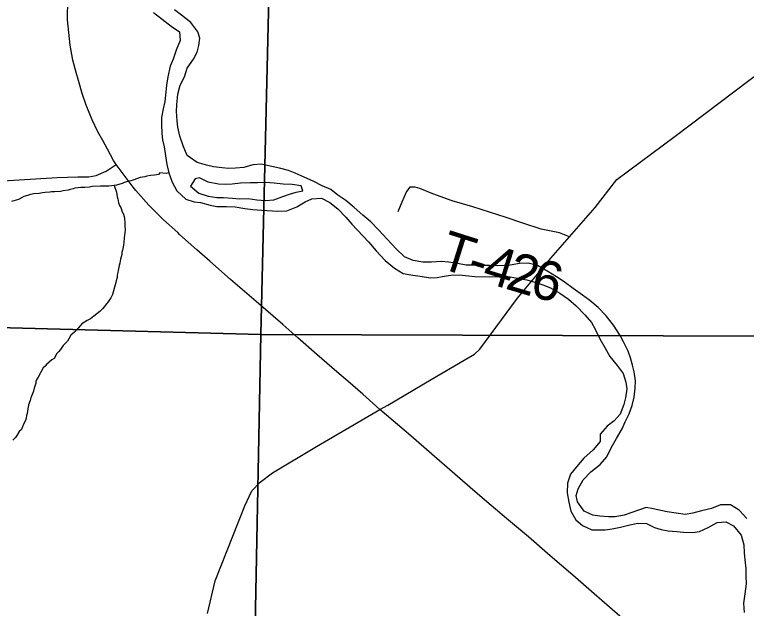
# Model space of a CAD drawing. Extents: x 0 to 34, y -2.3 to 22.
# Drawn here: x 5.006 to 6.069, y 17.952 to 18.814 of the extents above; entities that cross this region are included whole.
import ezdxf

# ---------------------------------------------------------------- set-up
doc = ezdxf.new("R2010")
doc.units = 0
for name, color, linetype in [('GM_X_County_Road', 7, 'Continuous'), ('GM_X_Major_River', 7, 'Continuous'), ('GM_X_Minor_River', 7, 'Continuous'), ('GM_X_Section', 7, 'Continuous'), ('GM_X_Township_Road', 7, 'Continuous'), ('GM_X_Township_Road_Text', 7, 'Continuous'), ('GM_X_US_Route', 7, 'Continuous')]:
    doc.layers.add(name, color=color, linetype=linetype)

msp = doc.modelspace()

# ---------------------------------------------------------------- linework, layer by layer
at = {"layer": 'GM_X_County_Road'}
for p, q in [((5.9656, 18.6376), (6.1106, 18.7475)), ((5.8806, 18.5744), (5.9656, 18.6376)), ((5.8491, 18.534), (5.8806, 18.5744)), ((5.812, 18.4912), (5.8491, 18.534)), ((5.7848, 18.4604), (5.812, 18.4912)), ((5.7365, 18.4021), (5.7848, 18.4604)), ((5.6899, 18.3394), (5.7365, 18.4021)), ((5.6819, 18.3282), (5.6899, 18.3394)), ((5.6741, 18.3209), (5.6819, 18.3282)), ((5.659, 18.3122), (5.6741, 18.3209)), ((5.6112, 18.2843), (5.659, 18.3122)), ((5.5479, 18.2468), (5.6112, 18.2843)), ((5.4446, 18.1868), (5.5363, 18.2406)), ((5.5363, 18.2406), (5.5479, 18.2468)), ((5.3805, 18.1488), (5.4446, 18.1868)), ((5.3628, 18.1351), (5.3805, 18.1488)), ((5.3507, 18.1225), (5.3628, 18.1351)), ((5.3403, 18.1007), (5.3507, 18.1225)), ((5.2972, 17.992), (5.3403, 18.1007)), ((5.286, 17.9445), (5.2972, 17.992))]:
    msp.add_line(p, q, dxfattribs=at)
at = {"layer": 'GM_X_Major_River'}
for p, q in [((5.2075, 18.8173), (5.2201, 18.8074)), ((5.2484, 18.813), (5.2384, 18.8209)), ((5.2201, 18.8074), (5.2335, 18.7971)), ((5.2618, 18.8028), (5.2484, 18.813)), ((5.272, 18.7891), (5.2618, 18.8028)), ((5.2335, 18.7971), (5.2454, 18.7888)), ((5.2454, 18.7888), (5.2462, 18.7762)), ((5.2748, 18.7796), (5.272, 18.7891)), ((5.2462, 18.7762), (5.2408, 18.7623)), ((5.2737, 18.7693), (5.2748, 18.7796)), ((5.2408, 18.7623), (5.2362, 18.7495)), ((5.2711, 18.7595), (5.2737, 18.7693)), ((5.2659, 18.7494), (5.2711, 18.7595)), ((5.2321, 18.739), (5.2287, 18.7239)), ((5.2362, 18.7495), (5.2321, 18.739)), ((5.2564, 18.7364), (5.2659, 18.7494)), ((5.2526, 18.7235), (5.2564, 18.7364)), ((5.2287, 18.7239), (5.2264, 18.7118)), ((5.2465, 18.7116), (5.2526, 18.7235)), ((5.2264, 18.7118), (5.2257, 18.7019)), ((5.2431, 18.6987), (5.2465, 18.7116)), ((5.2257, 18.7019), (5.2242, 18.6879)), ((5.2415, 18.6832), (5.2431, 18.6987)), ((5.2242, 18.6879), (5.2216, 18.6773)), ((5.2216, 18.6773), (5.2193, 18.6644)), ((5.2412, 18.6733), (5.2415, 18.6832)), ((5.242, 18.66), (5.2412, 18.6733)), ((5.2193, 18.6644), (5.2194, 18.6546)), ((5.2194, 18.6546), (5.2198, 18.6416)), ((5.2428, 18.6504), (5.242, 18.66)), ((5.2459, 18.6374), (5.2428, 18.6504)), ((5.2198, 18.6416), (5.2206, 18.6321)), ((5.2508, 18.6236), (5.2459, 18.6374)), ((5.2206, 18.6321), (5.223, 18.6221)), ((5.223, 18.6221), (5.2253, 18.6088)), ((5.2564, 18.6097), (5.2508, 18.6236)), ((5.2253, 18.6088), (5.2272, 18.5962)), ((5.2713, 18.5994), (5.2564, 18.6097)), ((5.2272, 18.5962), (5.2299, 18.5843)), ((5.2845, 18.5952), (5.2713, 18.5994)), ((5.2947, 18.593), (5.2845, 18.5952)), ((5.3072, 18.5915), (5.2947, 18.593)), ((5.3167, 18.5905), (5.3072, 18.5915)), ((5.327, 18.5909), (5.3167, 18.5905)), ((5.3391, 18.5921), (5.327, 18.5909)), ((5.3522, 18.5959), (5.3391, 18.5921)), ((5.364, 18.5967), (5.3522, 18.5959)), ((5.3772, 18.594), (5.364, 18.5967)), ((5.3908, 18.5913), (5.3772, 18.594)), ((5.4036, 18.5876), (5.3908, 18.5913)), ((5.2299, 18.5843), (5.2348, 18.5708)), ((5.4134, 18.5838), (5.4036, 18.5876)), ((5.4265, 18.5781), (5.4134, 18.5838)), ((5.2348, 18.5708), (5.2416, 18.5581)), ((5.268, 18.5756), (5.2616, 18.5651)), ((5.2745, 18.5769), (5.268, 18.5756)), ((5.2872, 18.5708), (5.2745, 18.5769)), ((5.3019, 18.5677), (5.2872, 18.5708)), ((5.3339, 18.5691), (5.3217, 18.5679)), ((5.348, 18.5698), (5.3339, 18.5691)), ((5.3586, 18.5699), (5.348, 18.5698)), ((5.3704, 18.5703), (5.3586, 18.5699)), ((5.3829, 18.5695), (5.3704, 18.5703)), ((5.3962, 18.5676), (5.3829, 18.5695)), ((5.4404, 18.5716), (5.4265, 18.5781)), ((5.4527, 18.5652), (5.4404, 18.5716)), ((5.2616, 18.5651), (5.2734, 18.5549)), ((5.3122, 18.5674), (5.3019, 18.5677)), ((5.3217, 18.5679), (5.3122, 18.5674)), ((5.4091, 18.5672), (5.3962, 18.5676)), ((5.422, 18.5653), (5.4091, 18.5672)), ((5.4149, 18.5564), (5.4244, 18.5584)), ((5.4244, 18.5584), (5.422, 18.5653)), ((5.4655, 18.5599), (5.4527, 18.5652)), ((5.4755, 18.552), (5.4655, 18.5599)), ((5.2416, 18.5581), (5.2546, 18.5463)), ((5.2734, 18.5549), (5.287, 18.5503)), ((5.287, 18.5503), (5.2995, 18.5484)), ((5.2995, 18.5484), (5.3094, 18.5485)), ((5.3094, 18.5485), (5.3226, 18.5473)), ((5.3826, 18.5452), (5.3957, 18.5498)), ((5.3957, 18.5498), (5.4053, 18.5533)), ((5.4053, 18.5533), (5.4149, 18.5564)), ((5.4871, 18.544), (5.4755, 18.552)), ((5.2546, 18.5463), (5.2666, 18.5421)), ((5.2666, 18.5421), (5.2761, 18.5411)), ((5.2761, 18.5411), (5.29, 18.5373)), ((5.29, 18.5373), (5.2999, 18.5355)), ((5.3226, 18.5473), (5.3321, 18.5467)), ((5.3321, 18.5467), (5.345, 18.5471)), ((5.345, 18.5471), (5.3579, 18.5452)), ((5.3579, 18.5452), (5.3704, 18.544)), ((5.3704, 18.544), (5.3826, 18.5452)), ((5.4161, 18.5347), (5.4281, 18.542)), ((5.4281, 18.542), (5.4377, 18.5466)), ((5.4377, 18.5466), (5.4518, 18.5473)), ((5.4518, 18.5473), (5.4638, 18.5413)), ((5.4638, 18.5413), (5.4753, 18.5318)), ((5.4993, 18.5342), (5.4871, 18.544)), ((5.2999, 18.5355), (5.3135, 18.5354)), ((5.3135, 18.5354), (5.3264, 18.5347)), ((5.3264, 18.5347), (5.3404, 18.5324)), ((5.3404, 18.5324), (5.3522, 18.5309)), ((5.3522, 18.5309), (5.3647, 18.5301)), ((5.3647, 18.5301), (5.3882, 18.5287)), ((5.3882, 18.5287), (5.4015, 18.5291)), ((5.4015, 18.5291), (5.4161, 18.5347)), ((5.4753, 18.5318), (5.4871, 18.5197)), ((5.5119, 18.5228), (5.4993, 18.5342)), ((5.4871, 18.5197), (5.4959, 18.5096)), ((5.5234, 18.5133), (5.5119, 18.5228)), ((5.4959, 18.5096), (5.5199, 18.4841)), ((5.5345, 18.5016), (5.5234, 18.5133)), ((5.5595, 18.4742), (5.5345, 18.5016)), ((5.5199, 18.4841), (5.5309, 18.4709)), ((5.5721, 18.4621), (5.5595, 18.4742)), ((5.5309, 18.4709), (5.5442, 18.4568)), ((5.5442, 18.4568), (5.5579, 18.4458)), ((5.5848, 18.4571), (5.5721, 18.4621)), ((5.5988, 18.4548), (5.5848, 18.4571)), ((5.6117, 18.4548), (5.5988, 18.4548)), ((5.6262, 18.4555), (5.6117, 18.4548)), ((5.6361, 18.4545), (5.6262, 18.4555)), ((5.6493, 18.4526), (5.6361, 18.4545)), ((5.6618, 18.4503), (5.6493, 18.4526)), ((5.7394, 18.4526), (5.7256, 18.4503)), ((5.7519, 18.453), (5.7394, 18.4526)), ((5.7655, 18.4499), (5.7519, 18.453)), ((5.5579, 18.4458), (5.5702, 18.4382)), ((5.6732, 18.45), (5.6618, 18.4503)), ((5.6827, 18.4497), (5.6732, 18.45)), ((5.6959, 18.4497), (5.6827, 18.4497)), ((5.7077, 18.4493), (5.6959, 18.4497)), ((5.7256, 18.4503), (5.7077, 18.4493)), ((5.7804, 18.4411), (5.7655, 18.4499)), ((5.5702, 18.4382), (5.5842, 18.4355)), ((5.5842, 18.4355), (5.5952, 18.4344)), ((5.5952, 18.4344), (5.6099, 18.4317)), ((5.6099, 18.4317), (5.6198, 18.4321)), ((5.6198, 18.4321), (5.6298, 18.4341)), ((5.6298, 18.4341), (5.6397, 18.4357)), ((5.6397, 18.4357), (5.6519, 18.4362)), ((5.6519, 18.4362), (5.6651, 18.4346)), ((5.6651, 18.4346), (5.6746, 18.434)), ((5.6746, 18.434), (5.6951, 18.4334)), ((5.6951, 18.4334), (5.705, 18.4338)), ((5.705, 18.4338), (5.716, 18.4339)), ((5.716, 18.4339), (5.7259, 18.4332)), ((5.7259, 18.4332), (5.7365, 18.4314)), ((5.7365, 18.4314), (5.7501, 18.4291)), ((5.7931, 18.4335), (5.7804, 18.4411)), ((5.8043, 18.426), (5.7931, 18.4335)), ((5.7501, 18.4291), (5.7614, 18.4257)), ((5.7614, 18.4257), (5.7734, 18.4216)), ((5.7734, 18.4216), (5.7843, 18.4174)), ((5.8173, 18.4165), (5.8043, 18.426)), ((5.7843, 18.4174), (5.7978, 18.4098)), ((5.7978, 18.4098), (5.8104, 18.4007)), ((5.8307, 18.4066), (5.8173, 18.4165)), ((5.8104, 18.4007), (5.8215, 18.3912)), ((5.8415, 18.399), (5.8307, 18.4066)), ((5.8538, 18.3888), (5.8415, 18.399)), ((5.8215, 18.3912), (5.8341, 18.3783)), ((5.8652, 18.3767), (5.8538, 18.3888)), ((5.8341, 18.3783), (5.844, 18.367)), ((5.844, 18.367), (5.8494, 18.3573)), ((5.8758, 18.363), (5.8652, 18.3767)), ((5.8494, 18.3573), (5.8562, 18.3431)), ((5.8856, 18.3483), (5.8758, 18.363)), ((5.8903, 18.3387), (5.8856, 18.3483)), ((5.8562, 18.3431), (5.8631, 18.3307)), ((5.8971, 18.3255), (5.8903, 18.3387)), ((5.8631, 18.3307), (5.8703, 18.3176)), ((5.9006, 18.3155), (5.8971, 18.3255)), ((5.8703, 18.3176), (5.8813, 18.3047)), ((5.9034, 18.3052), (5.9006, 18.3155)), ((5.8813, 18.3047), (5.8897, 18.293)), ((5.9057, 18.2952), (5.9034, 18.3052)), ((5.8897, 18.293), (5.8939, 18.2804)), ((5.908, 18.2822), (5.9057, 18.2952)), ((5.9073, 18.2716), (5.908, 18.2822)), ((5.8939, 18.2804), (5.8951, 18.2708)), ((5.9058, 18.2587), (5.9073, 18.2716)), ((5.8951, 18.2708), (5.8932, 18.2576)), ((5.8932, 18.2576), (5.891, 18.2478)), ((5.9031, 18.2463), (5.9058, 18.2587)), ((5.891, 18.2478), (5.8857, 18.2338)), ((5.8986, 18.2346), (5.9031, 18.2463)), ((5.8857, 18.2338), (5.877, 18.2242)), ((5.8929, 18.2226), (5.8986, 18.2346)), ((5.877, 18.2242), (5.8665, 18.2165)), ((5.8885, 18.2125), (5.8929, 18.2226)), ((5.8665, 18.2165), (5.8563, 18.2047)), ((5.8801, 18.1986), (5.8885, 18.2125)), ((5.8563, 18.2047), (5.8564, 18.1944)), ((5.8725, 18.1852), (5.8801, 18.1986)), ((5.8564, 18.1944), (5.8465, 18.1821)), ((5.8465, 18.1821), (5.8329, 18.17)), ((5.8664, 18.172), (5.8725, 18.1852)), ((5.8329, 18.17), (5.8222, 18.1574)), ((5.8565, 18.1609), (5.8664, 18.172)), ((5.8222, 18.1574), (5.8136, 18.1466)), ((5.8429, 18.1503), (5.8565, 18.1609)), ((5.8136, 18.1466), (5.809, 18.1338)), ((5.8319, 18.1388), (5.8429, 18.1503)), ((5.809, 18.1338), (5.8086, 18.1197)), ((5.8243, 18.1257), (5.8319, 18.1388)), ((5.8218, 18.1159), (5.8243, 18.1257)), ((5.8086, 18.1197), (5.8112, 18.106)), ((5.8238, 18.1064), (5.8218, 18.1159)), ((5.8112, 18.106), (5.8139, 18.093)), ((5.8333, 18.0932), (5.8238, 18.1064)), ((6.0311, 18.1022), (6.0184, 18.0969)), ((6.0459, 18.1021), (6.0311, 18.1022)), ((6.0583, 18.0945), (6.0459, 18.1021)), ((5.8139, 18.093), (5.8211, 18.0806)), ((5.846, 18.0871), (5.8333, 18.0932)), ((5.9027, 18.0911), (5.8912, 18.0873)), ((5.9135, 18.095), (5.9027, 18.0911)), ((5.9235, 18.0985), (5.9135, 18.095)), ((5.9333, 18.0963), (5.9235, 18.0985)), ((5.9537, 18.0919), (5.9333, 18.0963)), ((5.9669, 18.0904), (5.9537, 18.0919)), ((6.0039, 18.0935), (5.9912, 18.09)), ((6.0184, 18.0969), (6.0039, 18.0935)), ((6.0693, 18.0824), (6.0583, 18.0945)), ((5.8211, 18.0806), (5.8307, 18.0723)), ((5.8558, 18.0857), (5.846, 18.0871)), ((5.8687, 18.0849), (5.8558, 18.0857)), ((5.8782, 18.085), (5.8687, 18.0849)), ((5.8912, 18.0873), (5.8782, 18.085)), ((5.9802, 18.0881), (5.9669, 18.0904)), ((5.9912, 18.09), (5.9802, 18.0881)), ((5.8307, 18.0723), (5.8442, 18.0658)), ((5.8739, 18.0676), (5.8862, 18.0699)), ((5.8862, 18.0699), (5.8995, 18.073)), ((5.8995, 18.073), (5.911, 18.0757)), ((5.911, 18.0757), (5.9236, 18.0753)), ((5.9236, 18.0753), (5.9352, 18.0693)), ((6.0134, 18.0692), (6.0266, 18.0768)), ((6.0266, 18.0768), (6.0391, 18.0776)), ((6.0391, 18.0776), (6.0504, 18.0716)), ((6.0504, 18.0716), (6.0614, 18.0583)), ((5.8442, 18.0658), (5.8537, 18.0659)), ((5.8537, 18.0659), (5.8636, 18.066)), ((5.8636, 18.066), (5.8739, 18.0676)), ((5.9352, 18.0693), (5.9453, 18.0663)), ((5.9453, 18.0663), (5.9555, 18.0645)), ((5.9555, 18.0645), (5.9677, 18.0634)), ((5.9677, 18.0634), (5.9775, 18.0627)), ((5.9775, 18.0627), (5.9912, 18.0623)), ((5.9912, 18.0623), (6.0007, 18.0635)), ((6.0007, 18.0635), (6.0134, 18.0692)), ((6.0614, 18.0583), (6.0651, 18.0442)), ((6.0651, 18.0442), (6.0656, 18.0327)), ((6.0656, 18.0327), (6.0668, 18.0224)), ((6.0668, 18.0224), (6.0683, 18.0098)), ((6.0683, 18.0098), (6.068, 17.9992)), ((6.068, 17.9992), (6.0684, 17.9878)), ((6.0684, 17.9878), (6.0665, 17.973)), ((6.0665, 17.973), (6.0649, 17.9594)), ((6.0649, 17.9594), (6.0657, 17.946))]:
    msp.add_line(p, q, dxfattribs=at)
at = {"layer": 'GM_X_Minor_River'}
for p, q in [((5.2032, 18.5804), (5.1978, 18.5794)), ((5.2093, 18.5809), (5.2032, 18.5804)), ((5.215, 18.5819), (5.2093, 18.5809)), ((5.2169, 18.5843), (5.215, 18.5819)), ((5.2261, 18.5831), (5.2169, 18.5843)), ((5.2299, 18.5843), (5.2261, 18.5831)), ((5.1649, 18.5701), (5.1622, 18.5687)), ((5.1706, 18.5715), (5.1649, 18.5701)), ((5.1748, 18.5729), (5.1706, 18.5715)), ((5.1791, 18.5742), (5.1748, 18.5729)), ((5.1883, 18.5774), (5.1791, 18.5742)), ((5.1952, 18.5787), (5.1883, 18.5774)), ((5.1978, 18.5794), (5.1952, 18.5787)), ((5.0836, 18.5593), (5.0763, 18.558)), ((5.0867, 18.5599), (5.0836, 18.5593)), ((5.0909, 18.5613), (5.0867, 18.5599)), ((5.0936, 18.562), (5.0909, 18.5613)), ((5.102, 18.5629), (5.0936, 18.562)), ((5.105, 18.5628), (5.102, 18.5629)), ((5.108, 18.5631), (5.105, 18.5628)), ((5.1145, 18.5636), (5.108, 18.5631)), ((5.1187, 18.5643), (5.1145, 18.5636)), ((5.1309, 18.5647), (5.1187, 18.5643)), ((5.1366, 18.5649), (5.1309, 18.5647)), ((5.14, 18.5648), (5.1366, 18.5649)), ((5.1427, 18.5651), (5.14, 18.5648)), ((5.1503, 18.566), (5.1427, 18.5651)), ((5.1541, 18.5663), (5.1503, 18.566)), ((5.1503, 18.566), (5.1538, 18.5564)), ((5.1622, 18.5687), (5.1541, 18.5663)), ((5.016, 18.548), (5.0117, 18.5458)), ((5.0191, 18.5498), (5.016, 18.548)), ((5.0245, 18.5515), (5.0191, 18.5498)), ((5.0291, 18.5529), (5.0245, 18.5515)), ((5.034, 18.5539), (5.0291, 18.5529)), ((5.0416, 18.5544), (5.034, 18.5539)), ((5.0462, 18.5554), (5.0416, 18.5544)), ((5.0504, 18.5557), (5.0462, 18.5554)), ((5.0569, 18.5563), (5.0504, 18.5557)), ((5.0596, 18.5566), (5.0569, 18.5563)), ((5.0638, 18.5568), (5.0596, 18.5566)), ((5.0725, 18.5573), (5.0638, 18.5568)), ((5.0763, 18.558), (5.0725, 18.5573)), ((5.1538, 18.5564), (5.1548, 18.5495)), ((5.1548, 18.5495), (5.1558, 18.5465)), ((5.0117, 18.5458), (5.0014, 18.5427)), ((5.1558, 18.5465), (5.1568, 18.5407)), ((5.1568, 18.5407), (5.1582, 18.5369)), ((5.1582, 18.5369), (5.16, 18.5338)), ((5.16, 18.5338), (5.1621, 18.5277)), ((5.1621, 18.5277), (5.1639, 18.5242)), ((5.1639, 18.5242), (5.165, 18.5211)), ((5.165, 18.5211), (5.1656, 18.5173)), ((5.1656, 18.5173), (5.1662, 18.5127)), ((5.1662, 18.5127), (5.1661, 18.5063)), ((5.1661, 18.5063), (5.1663, 18.5025)), ((5.1658, 18.4968), (5.1657, 18.4937)), ((5.1663, 18.5025), (5.1658, 18.4968)), ((5.1652, 18.49), (5.1646, 18.4831)), ((5.1657, 18.4937), (5.1652, 18.49)), ((5.1641, 18.4794), (5.1628, 18.4722)), ((5.1646, 18.4831), (5.1641, 18.4794)), ((5.1618, 18.4658), (5.1606, 18.4624)), ((5.1619, 18.4684), (5.1618, 18.4658)), ((5.1628, 18.4722), (5.1619, 18.4684)), ((5.1588, 18.4533), (5.158, 18.4499)), ((5.1597, 18.459), (5.1588, 18.4533)), ((5.1606, 18.4624), (5.1597, 18.459)), ((5.1562, 18.4427), (5.1558, 18.4397)), ((5.158, 18.4499), (5.1562, 18.4427)), ((5.1548, 18.4325), (5.1535, 18.4276)), ((5.1549, 18.4356), (5.1548, 18.4325)), ((5.1558, 18.4397), (5.1549, 18.4356)), ((5.153, 18.425), (5.1509, 18.4182)), ((5.1535, 18.4276), (5.153, 18.425)), ((5.1509, 18.4182), (5.148, 18.4077)), ((5.1459, 18.4028), (5.1416, 18.3972)), ((5.148, 18.4077), (5.1459, 18.4028)), ((5.1392, 18.3939), (5.1341, 18.3872)), ((5.1416, 18.3972), (5.1392, 18.3939)), ((5.1298, 18.3828), (5.1208, 18.3762)), ((5.1341, 18.3872), (5.1298, 18.3828)), ((5.1112, 18.37), (5.1034, 18.3649)), ((5.1162, 18.3722), (5.1112, 18.37)), ((5.1208, 18.3762), (5.1162, 18.3722)), ((5.0983, 18.3586), (5.0928, 18.3531)), ((5.101, 18.362), (5.0983, 18.3586)), ((5.1034, 18.3649), (5.101, 18.362)), ((5.0877, 18.3487), (5.0849, 18.3431)), ((5.0928, 18.3531), (5.0877, 18.3487)), ((5.0829, 18.3401), (5.0763, 18.3335)), ((5.0849, 18.3431), (5.0829, 18.3401)), ((5.0727, 18.3279), (5.0695, 18.3242)), ((5.0763, 18.3335), (5.0727, 18.3279)), ((5.0632, 18.3149), (5.0601, 18.3127)), ((5.0652, 18.3182), (5.0632, 18.3149)), ((5.0668, 18.3216), (5.0652, 18.3182)), ((5.0695, 18.3242), (5.0668, 18.3216)), ((5.0503, 18.3035), (5.0476, 18.3013)), ((5.0523, 18.3061), (5.0503, 18.3035)), ((5.0601, 18.3127), (5.0523, 18.3061)), ((5.0476, 18.3013), (5.0403, 18.2878)), ((5.038, 18.2845), (5.0367, 18.2815)), ((5.0403, 18.2878), (5.038, 18.2845)), ((5.0345, 18.2717), (5.0333, 18.2671)), ((5.0366, 18.2788), (5.0345, 18.2717)), ((5.0367, 18.2815), (5.0366, 18.2788)), ((5.0316, 18.2623), (5.0296, 18.2574)), ((5.0333, 18.2671), (5.0316, 18.2623)), ((5.0283, 18.2536), (5.0262, 18.2476)), ((5.0296, 18.2574), (5.0283, 18.2536)), ((5.0249, 18.2416), (5.024, 18.2348)), ((5.0254, 18.2442), (5.0249, 18.2416)), ((5.0262, 18.2476), (5.0254, 18.2442)), ((5.0231, 18.2321), (5.0226, 18.228)), ((5.024, 18.2348), (5.0231, 18.2321)), ((5.0189, 18.2193), (5.0161, 18.2118)), ((5.0218, 18.2246), (5.0189, 18.2193)), ((5.0226, 18.228), (5.0218, 18.2246)), ((5.0126, 18.2085), (5.0093, 18.2029)), ((5.0161, 18.2118), (5.0126, 18.2085)), ((5.007, 18.1999), (5.0035, 18.1962)), ((5.0093, 18.2029), (5.007, 18.1999))]:
    msp.add_line(p, q, dxfattribs=at)
at = {"layer": 'GM_X_Section'}
for p, q in [((5.3873, 19.3604), (5.3638, 18.3497)), ((5.3638, 18.3497), (5.3873, 19.3604)), ((5.3638, 18.3497), (4.3586, 18.376)), ((4.3586, 18.376), (5.3638, 18.3497)), ((5.3638, 18.3497), (5.3441, 17.3523)), ((5.3441, 17.3523), (5.3638, 18.3497)), ((6.607, 18.3457), (5.3638, 18.3497)), ((5.3638, 18.3497), (6.607, 18.3457))]:
    msp.add_line(p, q, dxfattribs=at)
at = {"layer": 'GM_X_Township_Road'}
for p, q in [((5.1389, 18.5868), (5.1536, 18.5964)), ((5.1136, 18.5787), (5.1246, 18.5804)), ((5.1246, 18.5804), (5.1389, 18.5868)), ((4.8754, 18.5661), (5.0676, 18.5775)), ((5.0676, 18.5775), (5.098, 18.5783)), ((5.098, 18.5783), (5.1136, 18.5787)), ((5.58, 18.5633), (5.575, 18.5573)), ((5.5878, 18.5636), (5.58, 18.5633)), ((5.5944, 18.5616), (5.5878, 18.5636)), ((5.6135, 18.5537), (5.5944, 18.5616)), ((5.575, 18.5573), (5.5683, 18.5417)), ((5.6413, 18.5434), (5.6135, 18.5537)), ((5.5683, 18.5417), (5.5628, 18.5278)), ((5.6713, 18.5351), (5.6413, 18.5434)), ((5.7198, 18.5195), (5.6713, 18.5351)), ((5.744, 18.5113), (5.7198, 18.5195)), ((5.7706, 18.5027), (5.744, 18.5113)), ((5.7973, 18.4972), (5.7706, 18.5027)), ((5.812, 18.4912), (5.7973, 18.4972))]:
    msp.add_line(p, q, dxfattribs=at)
at = {"layer": 'GM_X_US_Route'}
for p, q in [((5.0827, 18.8065), (5.0831, 18.8367)), ((5.0866, 18.7698), (5.0827, 18.8065)), ((5.0907, 18.7481), (5.0866, 18.7698)), ((5.0952, 18.7299), (5.0907, 18.7481)), ((5.0985, 18.7182), (5.0952, 18.7299)), ((5.1042, 18.6993), (5.0985, 18.7182)), ((5.11, 18.6825), (5.1042, 18.6993)), ((5.1186, 18.6612), (5.11, 18.6825)), ((5.127, 18.6438), (5.1186, 18.6612)), ((5.134, 18.631), (5.127, 18.6438)), ((5.1407, 18.6185), (5.134, 18.631)), ((5.1498, 18.6023), (5.1407, 18.6185)), ((5.1536, 18.5964), (5.1498, 18.6023)), ((5.1783, 18.5636), (5.1536, 18.5964)), ((5.182, 18.5586), (5.1783, 18.5636)), ((5.2011, 18.5373), (5.182, 18.5586)), ((5.2222, 18.5161), (5.2011, 18.5373)), ((5.2428, 18.4976), (5.2222, 18.5161)), ((5.2456, 18.495), (5.2428, 18.4976)), ((5.2708, 18.4725), (5.2456, 18.495)), ((5.2895, 18.4559), (5.2708, 18.4725)), ((5.3197, 18.4296), (5.2895, 18.4559)), ((5.357, 18.3976), (5.3197, 18.4296)), ((5.3953, 18.3642), (5.357, 18.3976)), ((5.4174, 18.3447), (5.3953, 18.3642)), ((5.445, 18.3205), (5.4174, 18.3447)), ((5.474, 18.2952), (5.445, 18.3205)), ((5.4901, 18.2817), (5.474, 18.2952)), ((5.5119, 18.2631), (5.4901, 18.2817)), ((5.5363, 18.2406), (5.5119, 18.2631)), ((5.5813, 18.2026), (5.5363, 18.2406)), ((5.6121, 18.176), (5.5813, 18.2026)), ((5.6453, 18.1466), (5.6121, 18.176)), ((5.6747, 18.1213), (5.6453, 18.1466)), ((5.6984, 18.1011), (5.6747, 18.1213)), ((5.7203, 18.0824), (5.6984, 18.1011)), ((5.7523, 18.0558), (5.7203, 18.0824)), ((5.7841, 18.0283), (5.7523, 18.0558)), ((5.8166, 18.0002), (5.7841, 18.0283)), ((5.8476, 17.9729), (5.8166, 18.0002)), ((5.87, 17.9536), (5.8476, 17.9729)), ((5.8922, 17.9342), (5.87, 17.9536))]:
    msp.add_line(p, q, dxfattribs=at)

# ---------------------------------------------------------------- texts
at = {"layer": 'GM_X_Township_Road_Text'}
for s, rotation, p in [('T', 342.4067, (5.6198, 18.4472)), ('4', 342.7343, (5.6829, 18.4272)), ('2', 343.3641, (5.717, 18.4166)), ('-', 342.4768, (5.6604, 18.4343)), ('6', 345.0895, (5.7523, 18.4061))]:
    msp.add_text(s, height=0.0568, rotation=rotation, dxfattribs=at).set_placement(p)

doc.saveas('drawing.dxf')
